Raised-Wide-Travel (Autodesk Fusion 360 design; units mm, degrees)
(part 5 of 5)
sketch "Roller compensated wide travel cam" plane through (7, 0, 0) normal (1, 0, 0) x axis (0, 0, -1)
  line L1 (-48.5705, 45.6443) -> (-48.7661, 45.7338)
  line L2 (-48.3751, 45.554) -> (-48.5705, 45.6443)
  line L3 (-48.1798, 45.4628) -> (-48.3751, 45.554)
  line L4 (-47.9847, 45.3709) -> (-48.1798, 45.4628)
  line L5 (-47.7898, 45.2782) -> (-47.9847, 45.3709)
  line L6 (-47.595, 45.1848) -> (-47.7898, 45.2782)
  line L7 (-47.4003, 45.0906) -> (-47.595, 45.1848)
  line L8 (-47.2058, 44.9956) -> (-47.4003, 45.0906)
  line L9 (-47.0114, 44.8999) -> (-47.2058, 44.9956)
  line L10 (-46.8172, 44.8035) -> (-47.0114, 44.8999)
  line L11 (-46.6232, 44.7064) -> (-46.8172, 44.8035)
  line L12 (-46.4293, 44.6085) -> (-46.6232, 44.7064)
  line L13 (-46.2355, 44.51) -> (-46.4293, 44.6085)
  line L14 (-46.0419, 44.4108) -> (-46.2355, 44.51)
  line L15 (-45.8485, 44.311) -> (-46.0419, 44.4108)
  line L16 (-45.6552, 44.2105) -> (-45.8485, 44.311)
  line L17 (-45.4621, 44.1093) -> (-45.6552, 44.2105)
  line L18 (-45.2692, 44.0075) -> (-45.4621, 44.1093)
  line L19 (-45.0764, 43.9051) -> (-45.2692, 44.0075)
  line L20 (-44.8837, 43.8021) -> (-45.0764, 43.9051)
  line L21 (-44.6913, 43.6985) -> (-44.8837, 43.8021)
  line L22 (-44.4989, 43.5943) -> (-44.6913, 43.6985)
  line L23 (-44.3068, 43.4895) -> (-44.4989, 43.5943)
  line L24 (-44.1148, 43.3841) -> (-44.3068, 43.4895)
  line L25 (-43.923, 43.2782) -> (-44.1148, 43.3841)
  line L26 (-43.7314, 43.1717) -> (-43.923, 43.2782)
  line L27 (-43.5399, 43.0647) -> (-43.7314, 43.1717)
  line L28 (-43.3486, 42.9572) -> (-43.5399, 43.0647)
  line L29 (-43.1575, 42.8491) -> (-43.3486, 42.9572)
  line L30 (-42.9666, 42.7405) -> (-43.1575, 42.8491)
  line L31 (-42.7758, 42.6314) -> (-42.9666, 42.7405)
  line L32 (-42.5853, 42.5218) -> (-42.7758, 42.6314)
  line L33 (-42.3949, 42.4118) -> (-42.5853, 42.5218)
  line L34 (-42.2047, 42.3012) -> (-42.3949, 42.4118)
  line L35 (-42.0147, 42.1902) -> (-42.2047, 42.3012)
  line L36 (-41.8249, 42.0787) -> (-42.0147, 42.1902)
  line L37 (-41.6353, 41.9667) -> (-41.8249, 42.0787)
  line L38 (-41.4459, 41.8543) -> (-41.6353, 41.9667)
  line L39 (-41.2567, 41.7414) -> (-41.4459, 41.8543)
  line L40 (-41.0677, 41.6281) -> (-41.2567, 41.7414)
  line L41 (-40.8789, 41.5144) -> (-41.0677, 41.6281)
  line L42 (-40.6904, 41.4002) -> (-40.8789, 41.5144)
  line L43 (-40.502, 41.2856) -> (-40.6904, 41.4002)
  line L44 (-40.3139, 41.1705) -> (-40.502, 41.2856)
  line L45 (-40.1261, 41.0551) -> (-40.3139, 41.1705)
  line L46 (-39.9384, 40.9392) -> (-40.1261, 41.0551)
  line L47 (-39.751, 40.823) -> (-39.9384, 40.9392)
  line L48 (-39.5639, 40.7063) -> (-39.751, 40.823)
  line L49 (-39.377, 40.5892) -> (-39.5639, 40.7063)
  line L50 (-39.1903, 40.4718) -> (-39.377, 40.5892)
  line L51 (-39.0039, 40.3539) -> (-39.1903, 40.4718)
  line L52 (-38.8178, 40.2357) -> (-39.0039, 40.3539)
  line L53 (-38.632, 40.117) -> (-38.8178, 40.2357)
  line L54 (-38.4464, 39.998) -> (-38.632, 40.117)
  line L55 (-38.2611, 39.8786) -> (-38.4464, 39.998)
  line L56 (-38.0761, 39.7588) -> (-38.2611, 39.8786)
  line L57 (-37.8914, 39.6386) -> (-38.0761, 39.7588)
  line L58 (-37.7071, 39.518) -> (-37.8914, 39.6386)
  line L59 (-37.523, 39.3971) -> (-37.7071, 39.518)
  line L60 (-37.3392, 39.2757) -> (-37.523, 39.3971)
  line L61 (-37.1558, 39.154) -> (-37.3392, 39.2757)
  line L62 (-36.9727, 39.0319) -> (-37.1558, 39.154)
  line L63 (-36.7899, 38.9094) -> (-36.9727, 39.0319)
  line L64 (-36.6075, 38.7865) -> (-36.7899, 38.9094)
  line L65 (-36.4255, 38.6633) -> (-36.6075, 38.7865)
  line L66 (-36.2438, 38.5396) -> (-36.4255, 38.6633)
  line L67 (-36.0625, 38.4156) -> (-36.2438, 38.5396)
  line L68 (-35.8815, 38.2912) -> (-36.0625, 38.4156)
  line L69 (-35.701, 38.1664) -> (-35.8815, 38.2912)
  line L70 (-35.5208, 38.0412) -> (-35.701, 38.1664)
  line L71 (-35.3411, 37.9156) -> (-35.5208, 38.0412)
  line L72 (-35.1617, 37.7896) -> (-35.3411, 37.9156)
  line L73 (-34.9828, 37.6631) -> (-35.1617, 37.7896)
  line L74 (-34.8044, 37.5363) -> (-34.9828, 37.6631)
  line L75 (-34.6263, 37.4091) -> (-34.8044, 37.5363)
  line L76 (-34.4487, 37.2815) -> (-34.6263, 37.4091)
  line L77 (-34.2716, 37.1534) -> (-34.4487, 37.2815)
  line L78 (-34.095, 37.0249) -> (-34.2716, 37.1534)
  line L79 (-33.9188, 36.896) -> (-34.095, 37.0249)
  line L80 (-33.7431, 36.7667) -> (-33.9188, 36.896)
  line L81 (-33.5679, 36.6369) -> (-33.7431, 36.7667)
  line L82 (-33.3933, 36.5067) -> (-33.5679, 36.6369)
  line L83 (-33.2191, 36.3761) -> (-33.3933, 36.5067)
  line L84 (-33.0455, 36.245) -> (-33.2191, 36.3761)
  line L85 (-32.8724, 36.1134) -> (-33.0455, 36.245)
  line L86 (-32.6998, 35.9814) -> (-32.8724, 36.1134)
  line L87 (-32.5279, 35.8489) -> (-32.6998, 35.9814)
  line L88 (-32.3565, 35.716) -> (-32.5279, 35.8489)
  line L89 (-32.1856, 35.5826) -> (-32.3565, 35.716)
  line L90 (-32.0154, 35.4487) -> (-32.1856, 35.5826)
  line L91 (-31.8458, 35.3144) -> (-32.0154, 35.4487)
  line L92 (-31.6768, 35.1795) -> (-31.8458, 35.3144)
  line L93 (-31.5084, 35.0442) -> (-31.6768, 35.1795)
  line L94 (-31.3406, 34.9083) -> (-31.5084, 35.0442)
  line L95 (-31.1735, 34.772) -> (-31.3406, 34.9083)
  line L96 (-31.0071, 34.6351) -> (-31.1735, 34.772)
  line L97 (-30.8413, 34.4977) -> (-31.0071, 34.6351)
  line L98 (-30.6762, 34.3598) -> (-30.8413, 34.4977)
  line L99 (-30.5118, 34.2214) -> (-30.6762, 34.3598)
  line L100 (-30.3481, 34.0825) -> (-30.5118, 34.2214)
  line L101 (-30.1851, 33.943) -> (-30.3481, 34.0825)
  line L102 (-30.0228, 33.803) -> (-30.1851, 33.943)
  line L103 (-29.8612, 33.6624) -> (-30.0228, 33.803)
  line L104 (-29.7004, 33.5213) -> (-29.8612, 33.6624)
  line L105 (-29.5404, 33.3796) -> (-29.7004, 33.5213)
  line L106 (-29.3811, 33.2374) -> (-29.5404, 33.3796)
  line L107 (-29.2226, 33.0946) -> (-29.3811, 33.2374)
  line L108 (-29.0649, 32.9512) -> (-29.2226, 33.0946)
  line L109 (-28.908, 32.8073) -> (-29.0649, 32.9512)
  line L110 (-28.7519, 32.6628) -> (-28.908, 32.8073)
  line L111 (-28.5966, 32.5177) -> (-28.7519, 32.6628)
  line L112 (-28.4422, 32.372) -> (-28.5966, 32.5177)
  line L113 (-28.2886, 32.2257) -> (-28.4422, 32.372)
  line L114 (-28.1358, 32.0788) -> (-28.2886, 32.2257)
  line L115 (-27.984, 31.9314) -> (-28.1358, 32.0788)
  line L116 (-27.833, 31.7833) -> (-27.984, 31.9314)
  line L117 (-27.6828, 31.6346) -> (-27.833, 31.7833)
  line L118 (-27.5336, 31.4853) -> (-27.6828, 31.6346)
  line L119 (-27.3853, 31.3354) -> (-27.5336, 31.4853)
  line L120 (-27.2379, 31.1849) -> (-27.3853, 31.3354)
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extrude "Extrude1" new body sketch "Roller compensated wide travel cam" along normal blind 8 bodies "P08 Cam 3 gates - 116 degree span"
work_plane "WorkPlane2" AlongDistance 6.9 ExtraOffset 0
sketch "Cam screw clearance" plane through (6.9, 0, 0) normal (1, 0, 0) x axis (0, 0, -1)
  circle C1 centre (-39.5442, 25.4558) radius 1.7
extrude "Extrude2" cut sketch "Cam screw clearance" along normal blind 8.2
work_plane "WorkPlane3" AlongDistance 12 ExtraOffset 0
sketch "Cam head recess" plane through (12, 0, 0) normal (1, 0, 0) x axis (0, 0, -1)
  circle C1 centre (-39.5442, 25.4558) radius 3.1
extrude "Extrude3" cut sketch "Cam head recess" along normal blind 3.1
work_plane "WorkPlane4" AlongDistance 6.9 ExtraOffset 0
sketch "Cam screw clearance (1)" plane through (6.9, 0, 0) normal (1, 0, 0) x axis (0, 0, -1)
  circle C1 centre (-29, 0) radius 1.7
extrude "Extrude4" cut sketch "Cam screw clearance (1)" along normal blind 8.2
work_plane "WorkPlane5" AlongDistance 12 ExtraOffset 0
sketch "Cam head recess (1)" plane through (12, 0, 0) normal (1, 0, 0) x axis (0, 0, -1)
  circle C1 centre (-29, 0) radius 3.1
extrude "Extrude5" cut sketch "Cam head recess (1)" along normal blind 3.1
work_plane "WorkPlane6" AlongDistance 6.9 ExtraOffset 0
sketch "Cam screw clearance (2)" plane through (6.9, 0, 0) normal (1, 0, 0) x axis (0, 0, -1)
  circle C1 centre (-39.5442, -25.4558) radius 1.7
extrude "Extrude6" cut sketch "Cam screw clearance (2)" along normal blind 8.2
work_plane "WorkPlane7" AlongDistance 12 ExtraOffset 0
sketch "Cam head recess (2)" plane through (12, 0, 0) normal (1, 0, 0) x axis (0, 0, -1)
  circle C1 centre (-39.5442, -25.4558) radius 3.1
extrude "Extrude7" cut sketch "Cam head recess (2)" along normal blind 3.1
work_plane "WorkPlane1" AlongDistance 27.4 ExtraOffset 0
sketch "Measured body 11.2 x 9.5 x 6.6 excluding terminals" plane through (27.4, 0, 0) normal (1, 0, 0) x axis (0, 0, -1)
  line L1 (-105.4, 5.6) -> (-105.4, -5.6)
  line L2 (-114.9, 5.6) -> (-105.4, 5.6)
  line L3 (-114.9, -5.6) -> (-114.9, 5.6)
  line L4 (-105.4, -5.6) -> (-114.9, -5.6)
extrude "Extrude1" new body sketch "Measured body 11.2 x 9.5 x 6.6 excluding terminals" along normal blind 6.6 bodies "REFERENCE Geared pot user measured 2026-10-25"
work_plane "WorkPlane2" AlongDistance 34 ExtraOffset 0
sketch "M7 bushing length inferred 15 minus 8" plane through (34, 0, 0) normal (1, 0, 0) x axis (0, 0, -1)
  circle C1 centre (-110.15, 0) radius 3.5
extrude "Extrude2" add sketch "M7 bushing length inferred 15 minus 8" along normal blind 7
work_plane "WorkPlane3" AlongDistance 41 ExtraOffset 0
sketch "Measured rotating shaft diameter6 length8" plane through (41, 0, 0) normal (1, 0, 0) x axis (0, 0, -1)
  circle C1 centre (-110.15, 0) radius 3
extrude "Extrude3" add sketch "Measured rotating shaft diameter6 length8" along normal blind 8
position "Position5"
work_plane "WorkPlane106" AlongDistance 23.9 ExtraOffset 0
sketch "Wide cam service opening" plane through (23.9, 0, 0) normal (1, 0, 0) x axis (0, 0, -1)
  line L1 (-50.6669, 49.9856) -> (-52.4201, 50.4554)
  line L2 (-48.9311, 49.4549) -> (-50.6669, 49.9856)
  line L3 (-47.215, 48.864) -> (-48.9311, 49.4549)
  line L4 (-45.5205, 48.2136) -> (-47.215, 48.864)
  line L5 (-43.8497, 47.5044) -> (-45.5205, 48.2136)
  line L6 (-42.2047, 46.7373) -> (-43.8497, 47.5044)
  line L7 (-40.5875, 45.9133) -> (-42.2047, 46.7373)
  line L8 (-39, 45.0333) -> (-40.5875, 45.9133)
  line L9 (-37.4442, 44.0985) -> (-39, 45.0333)
  line L10 (-35.922, 43.11) -> (-37.4442, 44.0985)
  line L11 (-34.4352, 42.0689) -> (-35.922, 43.11)
  line L12 (-32.9856, 40.9766) -> (-34.4352, 42.0689)
  line L13 (-31.575, 39.8343) -> (-32.9856, 40.9766)
  line L14 (-30.2052, 38.6435) -> (-31.575, 39.8343)
  line L15 (-28.8778, 37.4057) -> (-30.2052, 38.6435)
  line L16 (-27.5943, 36.1222) -> (-28.8778, 37.4057)
  line L17 (-26.3565, 34.7948) -> (-27.5943, 36.1222)
  line L18 (-25.1657, 33.425) -> (-26.3565, 34.7948)
  line L19 (-24.0234, 32.0144) -> (-25.1657, 33.425)
  line L20 (-22.9311, 30.5648) -> (-24.0234, 32.0144)
  line L21 (-21.89, 29.078) -> (-22.9311, 30.5648)
  line L22 (-20.9015, 27.5558) -> (-21.89, 29.078)
  line L23 (-19.9667, 26) -> (-20.9015, 27.5558)
  line L24 (-19.0867, 24.4125) -> (-19.9667, 26)
  line L25 (-18.2627, 22.7953) -> (-19.0867, 24.4125)
  line L26 (-17.4956, 21.1503) -> (-18.2627, 22.7953)
  line L27 (-16.7864, 19.4795) -> (-17.4956, 21.1503)
  line L28 (-16.136, 17.785) -> (-16.7864, 19.4795)
  line L29 (-15.5451, 16.0689) -> (-16.136, 17.785)
  line L30 (-15.0144, 14.3331) -> (-15.5451, 16.0689)
  line L31 (-14.5446, 12.5799) -> (-15.0144, 14.3331)
  line L32 (-14.1363, 10.8114) -> (-14.5446, 12.5799)
  line L33 (-13.79, 9.0297) -> (-14.1363, 10.8114)
  line L34 (-13.5061, 7.237) -> (-13.79, 9.0297)
  line L35 (-13.2849, 5.4355) -> (-13.5061, 7.237)
  line L36 (-13.1267, 3.6273) -> (-13.2849, 5.4355)
  line L37 (-13.0317, 1.8148) -> (-13.1267, 3.6273)
  line L38 (-13, 0) -> (-13.0317, 1.8148)
  line L39 (-13.0317, -1.8148) -> (-13, 0)
  line L40 (-13.1267, -3.6273) -> (-13.0317, -1.8148)
  line L41 (-13.2849, -5.4355) -> (-13.1267, -3.6273)
  line L42 (-13.5061, -7.237) -> (-13.2849, -5.4355)
  line L43 (-13.79, -9.0297) -> (-13.5061, -7.237)
  line L44 (-14.1363, -10.8114) -> (-13.79, -9.0297)
  line L45 (-14.5446, -12.5799) -> (-14.1363, -10.8114)
  line L46 (-15.0144, -14.3331) -> (-14.5446, -12.5799)
  line L47 (-15.5451, -16.0689) -> (-15.0144, -14.3331)
  line L48 (-16.136, -17.785) -> (-15.5451, -16.0689)
  line L49 (-16.7864, -19.4795) -> (-16.136, -17.785)
  line L50 (-17.4956, -21.1503) -> (-16.7864, -19.4795)
  line L51 (-18.2627, -22.7953) -> (-17.4956, -21.1503)
  line L52 (-19.0867, -24.4125) -> (-18.2627, -22.7953)
  line L53 (-19.9667, -26) -> (-19.0867, -24.4125)
  line L54 (-20.9015, -27.5558) -> (-19.9667, -26)
  line L55 (-21.89, -29.078) -> (-20.9015, -27.5558)
  line L56 (-22.9311, -30.5648) -> (-21.89, -29.078)
  line L57 (-24.0234, -32.0144) -> (-22.9311, -30.5648)
  line L58 (-25.1657, -33.425) -> (-24.0234, -32.0144)
  line L59 (-26.3565, -34.7948) -> (-25.1657, -33.425)
  line L60 (-27.5943, -36.1222) -> (-26.3565, -34.7948)
  line L61 (-28.8778, -37.4057) -> (-27.5943, -36.1222)
  line L62 (-30.2052, -38.6435) -> (-28.8778, -37.4057)
  line L63 (-31.575, -39.8343) -> (-30.2052, -38.6435)
  line L64 (-32.9856, -40.9766) -> (-31.575, -39.8343)
  line L65 (-34.4352, -42.0689) -> (-32.9856, -40.9766)
  line L66 (-35.922, -43.11) -> (-34.4352, -42.0689)
  line L67 (-37.4442, -44.0985) -> (-35.922, -43.11)
  line L68 (-39, -45.0333) -> (-37.4442, -44.0985)
  line L69 (-40.5875, -45.9133) -> (-39, -45.0333)
  line L70 (-42.2047, -46.7373) -> (-40.5875, -45.9133)
  line L71 (-43.8497, -47.5044) -> (-42.2047, -46.7373)
  line L72 (-45.5205, -48.2136) -> (-43.8497, -47.5044)
  line L73 (-47.215, -48.864) -> (-45.5205, -48.2136)
  line L74 (-48.9311, -49.4549) -> (-47.215, -48.864)
  line L75 (-50.6669, -49.9856) -> (-48.9311, -49.4549)
  line L76 (-52.4201, -50.4554) -> (-50.6669, -49.9856)
  line L77 (-58.71, -25.2277) -> (-52.4201, -50.4554)
  line L78 (-57.8334, -24.9928) -> (-58.71, -25.2277)
  line L79 (-56.9656, -24.7275) -> (-57.8334, -24.9928)
  line L80 (-56.1075, -24.432) -> (-56.9656, -24.7275)
  line L81 (-55.2602, -24.1068) -> (-56.1075, -24.432)
  line L82 (-54.4248, -23.7522) -> (-55.2602, -24.1068)
  line L83 (-53.6024, -23.3686) -> (-54.4248, -23.7522)
  line L84 (-52.7937, -22.9566) -> (-53.6024, -23.3686)
  line L85 (-52, -22.5167) -> (-52.7937, -22.9566)
  line L86 (-51.2221, -22.0493) -> (-52, -22.5167)
  line L87 (-50.461, -21.555) -> (-51.2221, -22.0493)
  line L88 (-49.7176, -21.0344) -> (-50.461, -21.555)
  line L89 (-48.9928, -20.4883) -> (-49.7176, -21.0344)
  line L90 (-48.2875, -19.9172) -> (-48.9928, -20.4883)
  line L91 (-47.6026, -19.3218) -> (-48.2875, -19.9172)
  line L92 (-46.9389, -18.7028) -> (-47.6026, -19.3218)
  line L93 (-46.2972, -18.0611) -> (-46.9389, -18.7028)
  line L94 (-45.6782, -17.3974) -> (-46.2972, -18.0611)
  line L95 (-45.0828, -16.7125) -> (-45.6782, -17.3974)
  line L96 (-44.5117, -16.0072) -> (-45.0828, -16.7125)
  line L97 (-43.9656, -15.2824) -> (-44.5117, -16.0072)
  line L98 (-43.445, -14.539) -> (-43.9656, -15.2824)
  line L99 (-42.9507, -13.7779) -> (-43.445, -14.539)
  line L100 (-42.4833, -13) -> (-42.9507, -13.7779)
  line L101 (-42.0434, -12.2063) -> (-42.4833, -13)
  line L102 (-41.6314, -11.3976) -> (-42.0434, -12.2063)
  line L103 (-41.2478, -10.5752) -> (-41.6314, -11.3976)
  line L104 (-40.8932, -9.7398) -> (-41.2478, -10.5752)
  line L105 (-40.568, -8.8925) -> (-40.8932, -9.7398)
  line L106 (-40.2725, -8.0344) -> (-40.568, -8.8925)
  line L107 (-40.0072, -7.1666) -> (-40.2725, -8.0344)
  line L108 (-39.7723, -6.29) -> (-40.0072, -7.1666)
  line L109 (-39.5682, -5.4057) -> (-39.7723, -6.29)
  line L110 (-39.395, -4.5149) -> (-39.5682, -5.4057)
  line L111 (-39.253, -3.6185) -> (-39.395, -4.5149)
  line L112 (-39.1424, -2.7177) -> (-39.253, -3.6185)
  line L113 (-39.0633, -1.8137) -> (-39.1424, -2.7177)
  line L114 (-39.0158, -0.9074) -> (-39.0633, -1.8137)
  line L115 (-39, 0) -> (-39.0158, -0.9074)
  line L116 (-39.0158, 0.9074) -> (-39, 0)
  line L117 (-39.0633, 1.8137) -> (-39.0158, 0.9074)
  line L118 (-39.1424, 2.7177) -> (-39.0633, 1.8137)
  line L119 (-39.253, 3.6185) -> (-39.1424, 2.7177)
  line L120 (-39.395, 4.5149) -> (-39.253, 3.6185)
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extrude "Extrude106" cut sketch "Wide cam service opening" along normal blind 12.2 bodies "P02R Top-rail hanging right sensor sideplate (1)"
work_plane "WorkPlane107" AlongDistance 24 ExtraOffset 0
sketch "Upper bearing load bridge" plane through (24, 0, 0) normal (1, 0, 0) x axis (0, 0, -1)
  line L1 (-78, -20) -> (-78, -60)
  line L2 (-86, -20) -> (-78, -20)
  line L3 (-86, -60) -> (-86, -20)
  line L4 (-78, -60) -> (-86, -60)
extrude "Extrude107" add sketch "Upper bearing load bridge" along normal blind 12 bodies "P02R Top-rail hanging right sensor sideplate (1)"
work_plane "WorkPlane108" AlongDistance 24 ExtraOffset 0
sketch "Upper bearing load bridge (1)" plane through (24, 0, 0) normal (1, 0, 0) x axis (0, 0, -1)
  line L1 (-78, 60) -> (-78, 20)
  line L2 (-86, 60) -> (-78, 60)
  line L3 (-86, 20) -> (-86, 60)
  line L4 (-78, 20) -> (-86, 20)
extrude "Extrude108" add sketch "Upper bearing load bridge (1)" along normal blind 12
work_plane "WorkPlane109" AlongDistance 34 ExtraOffset 0
sketch "Restore sensor panel rebate after hanger rebuild" plane through (34, 0, 0) normal (1, 0, 0) x axis (0, 0, -1)
  line L1 (-3.8, 62.2) -> (-3.8, -62.2)
  line L2 (-34.2, 62.2) -> (-3.8, 62.2)
  line L3 (-34.2, -62.2) -> (-34.2, 62.2)
  line L4 (-3.8, -62.2) -> (-34.2, -62.2)
extrude "Extrude109" cut sketch "Restore sensor panel rebate after hanger rebuild" along normal blind 2.1
position "Position6"
work_plane "WorkPlane110" AlongDistance 24 ExtraOffset 0
sketch "Volumetric bridge to hanger overlap" plane through (24, 0, 0) normal (1, 0, 0) x axis (0, 0, -1)
  line L1 (-78, -57) -> (-78, -66)
  line L2 (-86, -57) -> (-78, -57)
  line L3 (-86, -66) -> (-86, -57)
  line L4 (-78, -66) -> (-86, -66)
extrude "Extrude110" add sketch "Volumetric bridge to hanger overlap" along normal blind 12
work_plane "WorkPlane111" AlongDistance 24 ExtraOffset 0
sketch "Volumetric bridge to hanger overlap (1)" plane through (24, 0, 0) normal (1, 0, 0) x axis (0, 0, -1)
  line L1 (-78, 66) -> (-78, 57)
  line L2 (-86, 66) -> (-78, 66)
  line L3 (-86, 57) -> (-86, 66)
  line L4 (-78, 57) -> (-86, 57)
extrude "Extrude111" add sketch "Volumetric bridge to hanger overlap (1)" along normal blind 12
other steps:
create_component "CreateComponent1"
create_component "CreateComponent2"
create_component "CreateComponent3"
create_component "CreateComponent4"
create_component "CreateComponent5"
create_component "CreateComponent7"
create_component "CreateComponent8"
create_component "CreateComponent12"
create_component "CreateComponent13"
create_component "CreateComponent14"
create_component "CreateComponent16"
create_component "CreateComponent28"
create_component "CreateComponent29"
create_component "CreateComponent49"
create_component "CreateComponent89"
create_component "CreateComponent90"
create_component "CreateComponent144"
create_component "CreateComponent145"
create_component "CreateComponent146"
create_component "CreateComponent147"
create_component "CreateComponent152"
create_component "CreateComponent153"
create_component "CreateComponent154"
create_component "CreateComponent155"
create_component "CreateComponent156"
create_component "CreateComponent157"
create_component "CreateComponent158"
create_component "CreateComponent159"
create_component "CreateComponent160"
create_component "CreateComponent161"
create_component "CreateComponent171"
create_component "CreateComponent172"
create_component "CreateComponent173"
create_component "CreateComponent174"
create_component "CreateComponent175"
create_component "CreateComponent176"
create_component "CreateComponent177"
create_component "CreateComponent178"
create_component "CreateComponent179"
create_component "CreateComponent180"
create_component "CreateComponent181"
create_component "CreateComponent182"
create_component "CreateComponent183"
create_component "CreateComponent184"
create_component "CreateComponent185"
create_component "CreateComponent186"
create_component "CreateComponent188"
create_component "CreateComponent194"
create_component "CreateComponent195"
create_component "CreateComponent196"
create_component "CreateComponent201"
create_component "CreateComponent202"
create_component "CreateComponent203"
create_component "CreateComponent204"
create_component "CreateComponent206"
create_component "CreateComponent207"
create_component "CreateComponent208"
create_component "CreateComponent209"
create_component "CreateComponent211"
create_component "CreateComponent212"
create_component "CreateComponent213"
create_component "CreateComponent214"
create_component "CreateComponent215"
create_component "CreateComponent216"
create_component "CreateComponent217"
create_component "CreateComponent218"
create_component "CreateComponent219"
named bodies: "P01R Top-rail hanging left sideplate", "P02R Top-rail hanging right sensor sideplate", "P03 Left flanged journal bush", "P04 Right flanged journal bush", "P06 Shaft retaining cap", "P07 Integral lever rotor and cam carrier", "P09 Grip insert half", "P10 Grip screw half", "P11 Forked roller follower", "P13 Spring reaction crossblock", "P21 Follower left axial spacer", "P22 Follower right axial spacer", "HARDWARE Roller axle M3 nut", "P23 Left rotor thrust spacer", "P24 Right rotor thrust spacer", "P25 Captured printed pivot lower half", "P26 Captured printed pivot upper half", "HARDWARE Grip M3x20 cap head 180", "HARDWARE Grip M3x20 cap head 190", "HARDWARE 623ZZ roller bearing at 8", "HARDWARE 623ZZ roller bearing at 12", "P27 Printed guide sleeve 4", "HARDWARE Cup guide M3x12 4", "P27 Printed guide sleeve 20", "HARDWARE Cup guide M3x12 20", "P14 Captive spring cup for 9 mm spring", "P15 Recessed preload limit collar 1 mm", "HARDWARE Preload M3x20 cap head", "REFERENCE Stock spring OD9 wire1 free20 - rate and solid height assumed", "HARDWARE Shaft joining M3x8 -15", "HARDWARE Shaft joining M3x8 15", "P28 Shaft alignment key -5", "P28 Shaft alignment key 5", "HARDWARE Main shaft cap M3x8 cap head", "HARDWARE Cam M3x10 cap head -45", "HARDWARE Cam M3x10 cap head 0", "HARDWARE Cam M3x10 cap head 45", "HARDWARE Roller axle M3x20 cap head", "HARDWARE Crossblock M3x20 cap head (-62, -1)", "HARDWARE Crossblock M3x20 cap head (-62, 1)", "HARDWARE Crossblock M3x20 cap head (-70, -1)", "HARDWARE Crossblock M3x20 cap head (-70, 1)", "HARDWARE Rotor clamp M3x16 cap head", "P05G Shaft lower half", "P05G Shaft upper half", "G01R 48T gear with upper clamp", "G02 24T sensor pinion", "HARDWARE Geared RK097 supplied washer ASSUMED", "HARDWARE Geared RK097 supplied nut ASSUMED", "HARDWARE G02 24T sensor pinion clamp M3x12", "HARDWARE G01 upper clamp M3x12", "G03R Lower removable potentiometer panel", "HARDWARE Lower panel M3x12 -55", "HARDWARE Lower panel M3x12 55", "HARDWARE Top hanging rail M5x14 (-30, -1)", "HARDWARE Top hanging rail M5x14 (-30, 1)", "HARDWARE Top hanging rail M5x14 (30, -1)", "HARDWARE Top hanging rail M5x14 (30, 1)", "HARDWARE Stop M3x20 cap head -1", "HARDWARE Stop M3 plain captive nut -1"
